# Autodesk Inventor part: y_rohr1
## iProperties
Created: 2005-04
Part Number: y_rohr1
Cost Center: 0 kg
Material: 1.0037 St 37-2
Document SubType Name: Modeling
Designer: juergen
Authority: 0 mm^3
Manufacturer: Standard
Standards Organization: Custom
Author: juergen
SaveDate: 2004-12-09
SaveTime: 10:15
TotalMass: 0 kg
TotalVolume: 0 mm^3
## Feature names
1. Sweeping1
2. Spiegeln1 [Mirror]
3. Rundung1 [Fillet]
4. Wandstärke1
